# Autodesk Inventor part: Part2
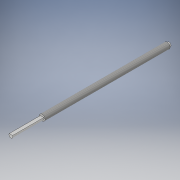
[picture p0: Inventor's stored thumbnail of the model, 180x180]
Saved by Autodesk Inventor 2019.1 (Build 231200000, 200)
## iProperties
Created: 2018-09
Part Number: Part2
Material: Generic
Document SubType Name: Modeling
Designer: drawing
Density: 1 g/cm^3
Appearance: Default
Author: drawing
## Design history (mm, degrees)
sketch "Sketch1"
  geometry: C1 r 4.763 at (0, 0); 1 further point
  constraints: 1 centre point, 1 coincident
  dimensions: "d0" = 9.525 diameter of C1
extrude "Extrusion1" new body sketch "Sketch1" stored distance "d1" = 254; taper "d2" = 0 deg
thread "Thread1" dims "d3" = 25.4, "d4" = 0
sketch "Sketch2"
  geometry: L1 (-2.75, 1.588)-(2.75, 1.588); C1 r 8.108 at (0, 0); A1 r 3.175 centre (0, 0) between (-2.75, 1.588) and (2.75, 1.588); 1 further point
  constraints: 2 centre point, 2 coincident, 2 end point, 2 point on circle, 1 horizontal
  dimensions: "d5" = 6.35 diameter of A1; "d6" = 1.5875 distance from line of point (0, 0) L1
extrude "Extrusion2" cut sketch "Sketch2" distance "d7" = 50.8; taper "d8" = 0 deg
sketch "Sketch4"
  geometry: C1 r 3.175 at (0, 0); 1 further point
  constraints: 1 centre point, 1 coincident
  dimensions: "d16" = 6.35 diameter of C1
extrude "Extrusion3" join sketch "Sketch4" distance "d17" = 3.175; taper "d18" = 0 deg
body "Solid1"
